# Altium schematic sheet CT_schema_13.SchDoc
size 382 x 278 mm
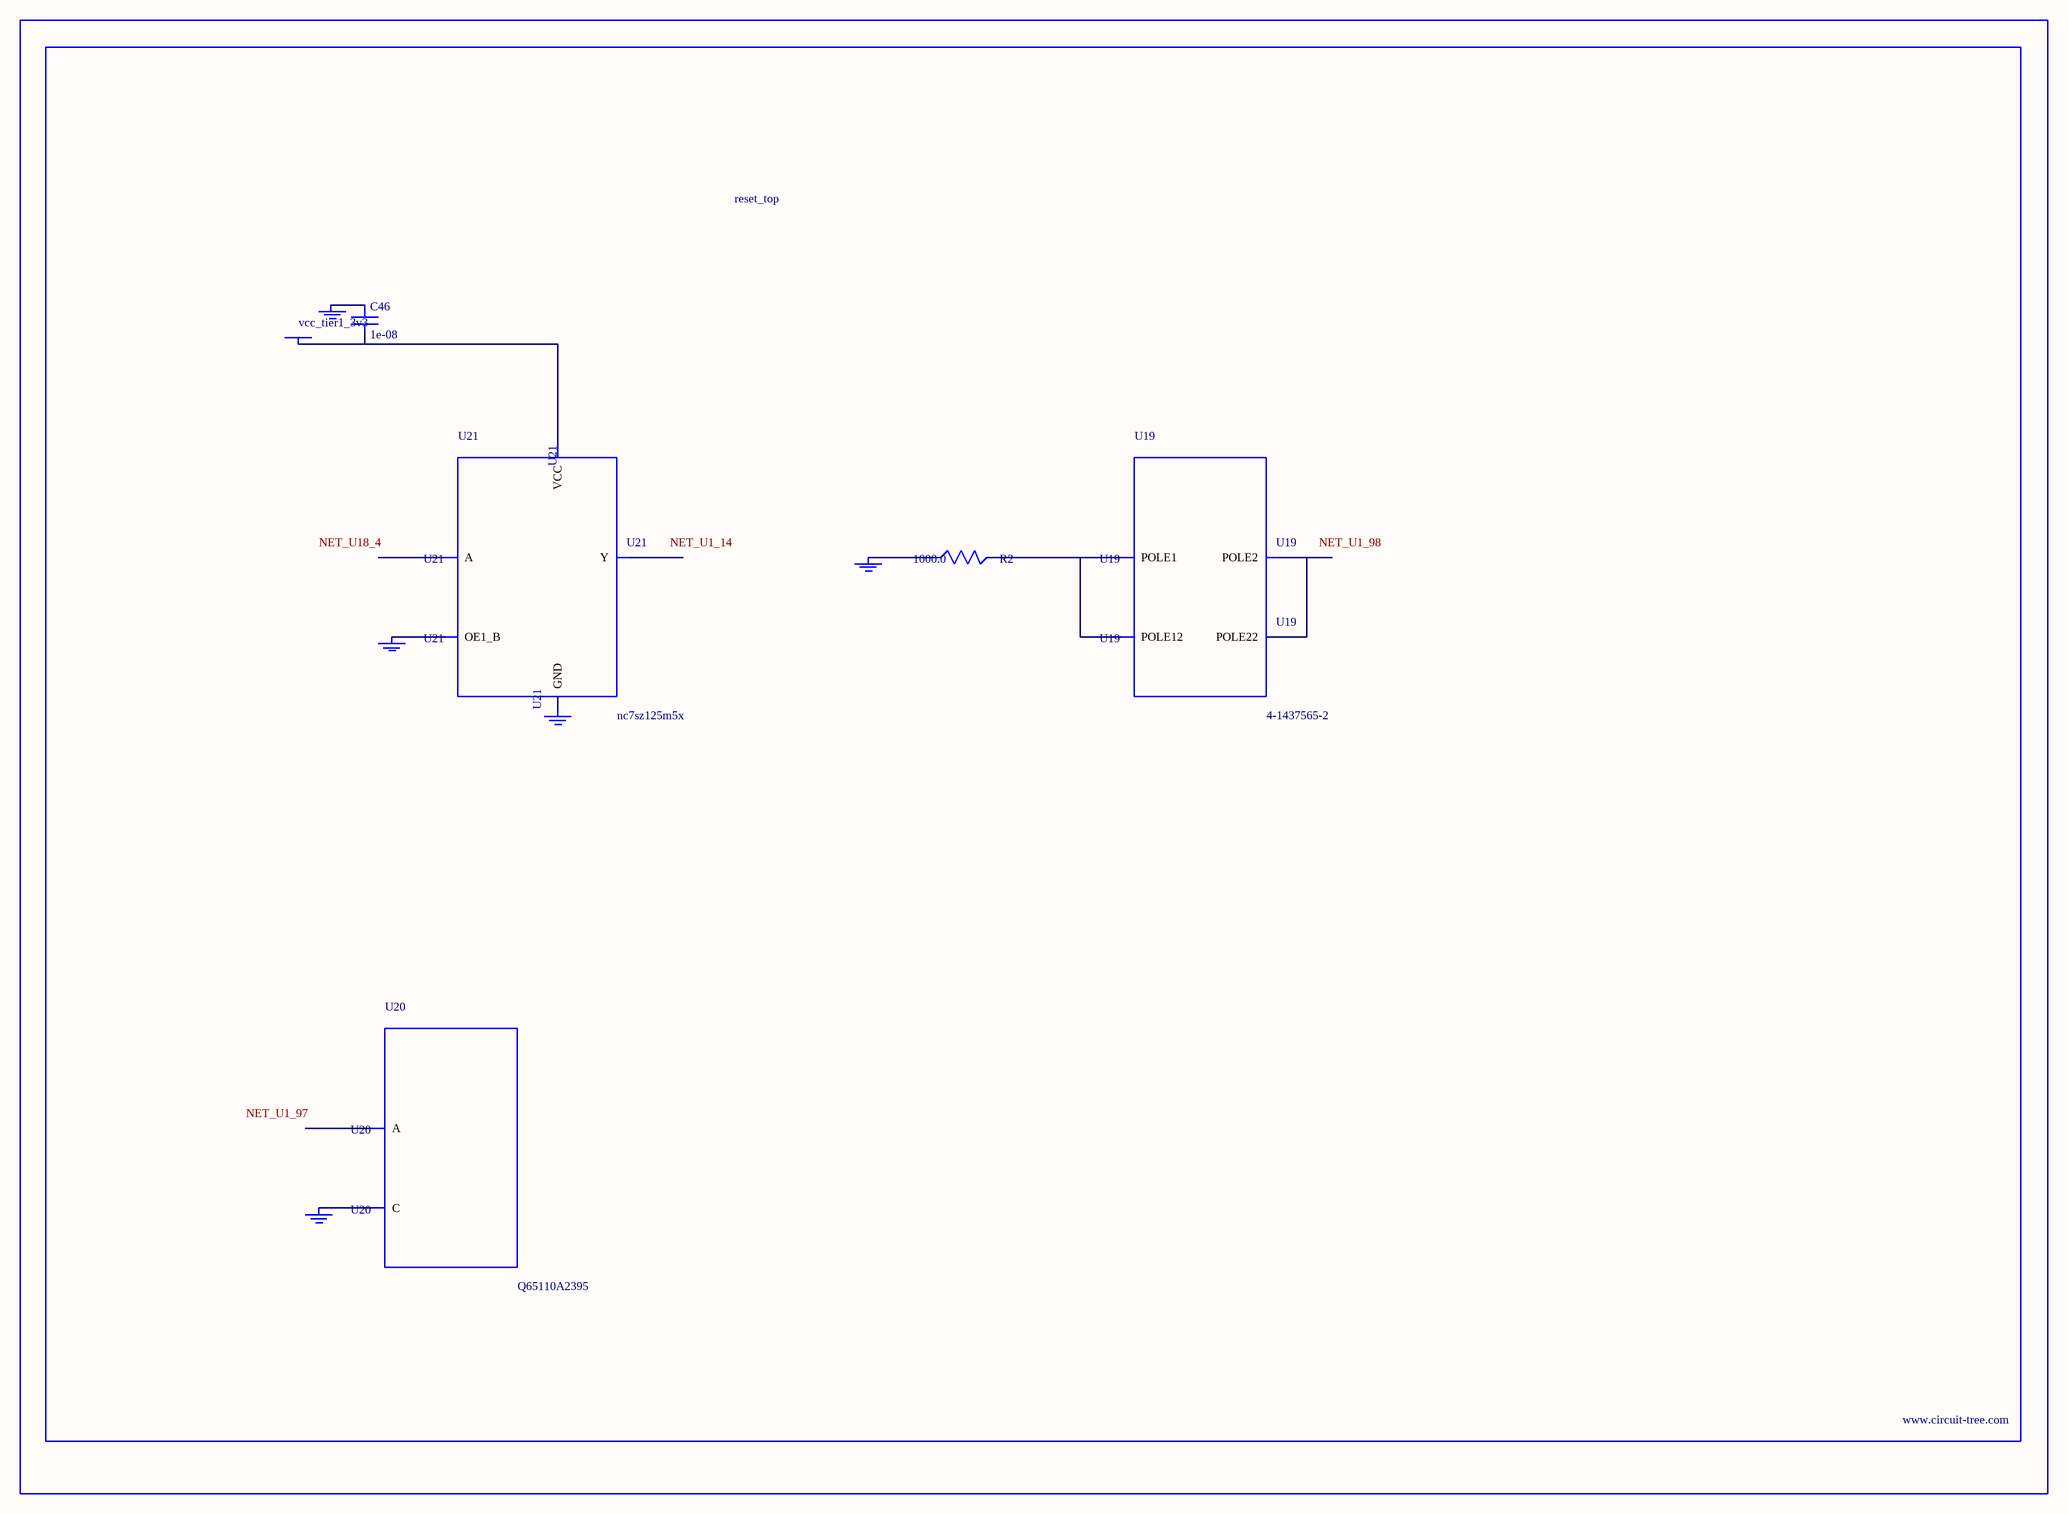
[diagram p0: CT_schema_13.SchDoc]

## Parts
BORDER12  (no value)
C46  1e-08  [C0402]
GND_INSTANCE_12_0  (no value)
GND_INSTANCE_12_1  (no value)
GND_INSTANCE_12_2  (no value)
GND_INSTANCE_12_3  (no value)
GND_INSTANCE_12_4  (no value)
POWER_INSTANCE_12_0  vcc_tier1_3v3
R2  1000.0  [R0603]
U19  4-1437565-2  [SW_4-1437565-2]
U20  Q65110A2395  [LGM67K-G1J2-24-Z]
U21  nc7sz125m5x  [NC7SZ125M5X]

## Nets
NetC46_1: C46.1 GND_INSTANCE_12_2.0(GND)
NetC46_2: C46.2 POWER_INSTANCE_12_0.0(PWR) U21.5(VCC)
NetGND_INSTANCE_12_0_0: GND_INSTANCE_12_0.0(GND) R2.1
NetGND_INSTANCE_12_1_0: GND_INSTANCE_12_1.0(GND) U20.C
NetGND_INSTANCE_12_3_0: GND_INSTANCE_12_3.0(GND) U21.1(OE1_B)
NetGND_INSTANCE_12_4_0: GND_INSTANCE_12_4.0(GND) U21.3(GND)
NetR2_2: R2.2 U19.1(POLE1) U19.2(POLE12)
NetU19_3: U19.3(POLE2) U19.4(POLE22)

Not connected (* = marked no-connect by the designer): U20 A; U21 2(A) 4(Y)

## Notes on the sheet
- Labels drawn without touching a wire or pin: NET_U1_14, NET_U1_97, NET_U1_98, NET_U18_4

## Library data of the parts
BORDER12 = BORDER_PAGE12
C46 = C0402C103K3RAC
GND_INSTANCE_12_0-GND_INSTANCE_12_4 = GND
POWER_INSTANCE_12_0 = PWR
R2 = RC0603JR-071KL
